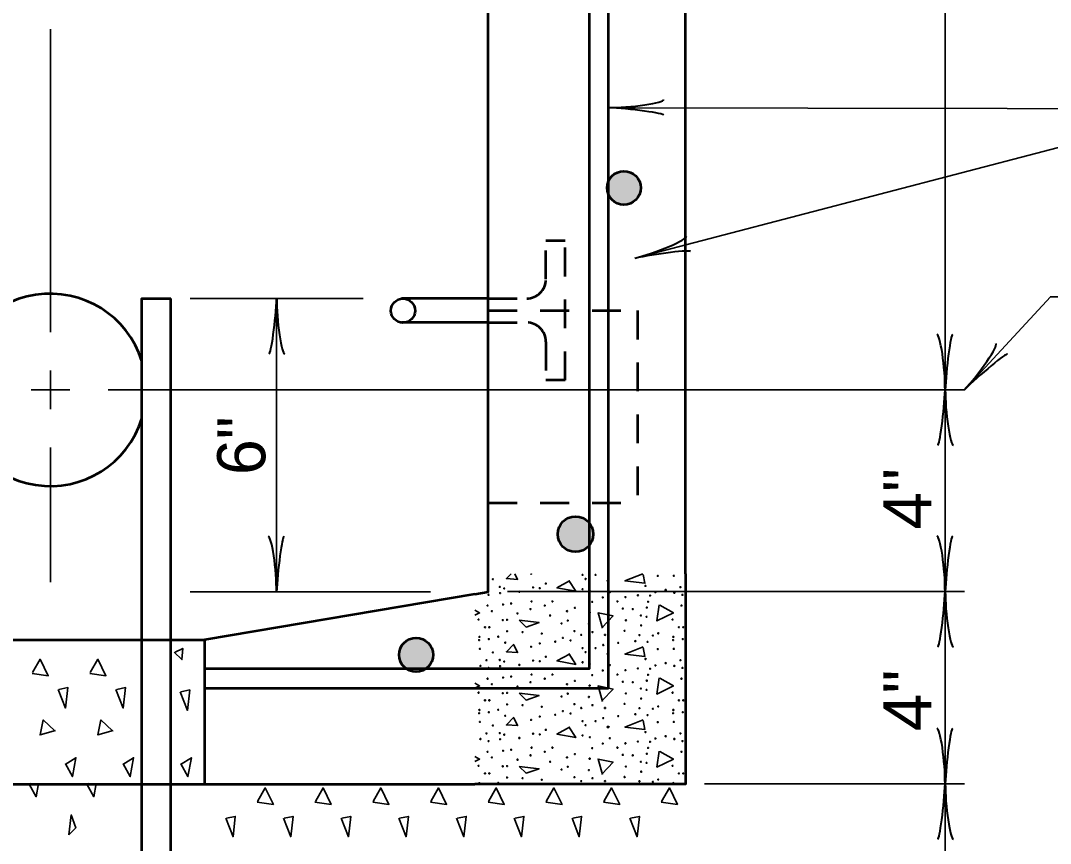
# Model space of a CAD drawing. Extents: x 788 to 1469, y -1 to 439.
# Drawn here: x 915.8 to 969.3, y 118.6 to 161.4 of the extents above; entities that cross this region are included whole.
import ezdxf

# ---------------------------------------------------------------- set-up
doc = ezdxf.new("R2010")
doc.units = 0
doc.linetypes.add('SHORT_DASHED', pattern=[2.7, 1.5, -1.2])
doc.layers.add('1', color=7, linetype='Continuous', lineweight=35)

msp = doc.modelspace()

# ---------------------------------------------------------------- hatches: boundary and pattern name
at = {"layer": '1'}
for points in [[(946.283, 152.704, 1), (948.034, 152.704, 1)], [(943.721, 134.704, 1), (945.568, 134.704, 1)], [(935.473, 128.43, 1), (937.243, 128.43, 1)]]:
    msp.add_hatch(color=256, dxfattribs=at).paths.add_polyline_path(points)

# ---------------------------------------------------------------- linework, layer by layer
at = {"layer": '1', "lineweight": 53}
for p, q in [((940.106, 132.643), (940.106, 165.102)), ((950.356, 132.643), (950.356, 165.102)), ((923.606, 112.203), (923.606, 146.953)), ((940.106, 146.953), (935.606, 146.953)), ((940.106, 145.703), (935.606, 145.703)), ((939.409, 131.585), (925.356, 129.203)), ((909.356, 129.203), (925.356, 129.203)), ((925.356, 129.203), (925.356, 121.703)), ((894.126, 121.703), (939.409, 121.703))]:
    msp.add_line(p, q, dxfattribs=at)
at = {"layer": '1'}
for p, q in [((917.356, 160.953), (917.356, 145.203)), ((933.606, 146.953), (924.606, 146.953)), ((929.106, 146.953), (929.106, 131.703)), ((917.356, 143.203), (917.356, 141.203)), ((916.356, 142.203), (918.356, 142.203)), ((920.356, 142.203), (964.856, 142.203)), ((917.356, 139.203), (917.356, 132.203)), ((937.106, 131.703), (924.606, 131.703)), ((941.106, 131.723), (964.856, 131.723)), ((916.333, 121.738), (916.231, 121.673)), ((919.333, 121.738), (919.231, 121.673)), ((951.356, 121.729), (964.856, 121.729))]:
    msp.add_line(p, q, dxfattribs=at)
at = {"layer": '1', "linetype": 'SHORT_DASHED', "lineweight": 53}
for p, q in [((943.106, 147.953), (943.106, 149.953)), ((940.106, 146.953), (942.106, 146.953)), ((940.106, 146.328), (947.866, 146.328)), ((947.866, 146.328), (947.866, 136.328)), ((940.106, 145.703), (942.106, 145.703)), ((943.106, 144.703), (943.106, 142.703)), ((944.106, 142.703), (943.106, 142.703)), ((940.106, 136.328), (947.866, 136.328))]:
    msp.add_line(p, q, dxfattribs=at)
at = {"layer": '1'}
for points in [[(963.856, 195.872), (963.856, 142.203), (963.856, 131.723), (963.856, 121.729), (963.856, 90.479)], [(947.731, 149.041), (977.44, 156.814), (946.356, 156.871)], [(964.856, 142.203), (969.329, 147.043), (972.657, 147.043)], [(941.293, 132.643), (941.054, 132.392), (941.634, 132.352), (941.488, 132.643)], [(944.334, 132.272), (943.674, 131.912), (944.654, 131.732), (944.294, 132.292)], [(948.134, 132.643), (947.214, 132.272), (948.254, 132.152), (948.154, 132.612)], [(939.409, 130.752), (939.654, 130.612), (939.409, 130.492)], [(946.054, 129.812), (945.814, 130.612), (946.594, 130.452), (946.034, 129.852)], [(949.034, 131.012), (949.734, 130.612), (948.874, 130.192), (948.994, 131.032)], [(923.787, 128.568), (924.187, 128.188), (924.227, 128.768), (923.827, 128.568)], [(941.434, 128.992), (941.054, 128.592), (941.634, 128.552), (941.434, 128.952)], [(944.334, 128.472), (943.674, 128.112), (944.654, 127.932), (944.294, 128.492)], [(948.154, 128.852), (947.214, 128.472), (948.254, 128.352), (948.154, 128.812)], [(916.417, 127.505), (916.817, 128.205), (917.237, 127.345), (916.397, 127.465)], [(919.417, 127.505), (919.817, 128.205), (920.237, 127.345), (919.397, 127.465)], [(939.409, 126.952), (939.654, 126.812), (939.409, 126.692)], [(949.034, 127.212), (949.734, 126.812), (948.874, 126.392), (948.994, 127.232)], [(917.757, 126.625), (918.137, 125.665), (918.257, 126.725), (917.797, 126.625)], [(920.757, 126.625), (921.137, 125.665), (921.257, 126.725), (920.797, 126.625)], [(924.097, 126.506), (924.477, 125.546), (924.597, 126.606), (924.137, 126.506)], [(946.054, 126.012), (945.814, 126.812), (946.594, 126.652), (946.034, 126.052)], [(917.617, 124.505), (916.817, 124.265), (916.977, 125.045), (917.577, 124.485)], [(920.617, 124.505), (919.817, 124.265), (919.977, 125.045), (920.577, 124.485)], [(941.434, 125.192), (941.054, 124.792), (941.634, 124.752), (941.434, 125.152)], [(948.154, 125.052), (947.214, 124.672), (948.254, 124.552), (948.154, 125.012)], [(944.334, 124.672), (943.674, 124.312), (944.654, 124.132), (944.294, 124.692)], [(939.409, 123.152), (939.654, 123.012), (939.409, 122.892)], [(949.034, 123.412), (949.734, 123.012), (948.874, 122.592), (948.994, 123.432)], [(918.137, 122.765), (918.497, 122.105), (918.677, 123.085), (918.117, 122.725)], [(921.137, 122.765), (921.497, 122.105), (921.677, 123.085), (921.117, 122.725)], [(924.137, 122.765), (924.497, 122.105), (924.677, 123.085), (924.117, 122.725)], [(946.054, 122.212), (945.814, 123.012), (946.594, 122.852), (946.034, 122.252)], [(916.251, 121.713), (916.611, 121.053), (916.737, 121.738)], [(919.251, 121.713), (919.611, 121.053), (919.737, 121.738)], [(928.121, 120.813), (928.521, 121.513), (928.942, 120.653), (928.101, 120.773)], [(931.121, 120.813), (931.521, 121.513), (931.942, 120.653), (931.101, 120.773)], [(934.121, 120.813), (934.521, 121.513), (934.942, 120.653), (934.101, 120.773)], [(937.121, 120.813), (937.521, 121.513), (937.942, 120.653), (937.101, 120.773)], [(940.121, 120.813), (940.521, 121.513), (940.942, 120.653), (940.101, 120.773)], [(943.121, 120.813), (943.521, 121.513), (943.942, 120.653), (943.101, 120.773)], [(946.121, 120.813), (946.521, 121.513), (946.942, 120.653), (946.101, 120.773)], [(949.121, 120.813), (949.521, 121.513), (949.942, 120.653), (949.101, 120.773)], [(926.462, 119.933), (926.841, 118.973), (926.962, 120.033), (926.501, 119.933)], [(929.462, 119.933), (929.841, 118.973), (929.962, 120.033), (929.501, 119.933)], [(932.462, 119.933), (932.841, 118.973), (932.962, 120.033), (932.501, 119.933)], [(935.462, 119.933), (935.841, 118.973), (935.962, 120.033), (935.501, 119.933)], [(938.462, 119.933), (938.841, 118.973), (938.962, 120.033), (938.501, 119.933)], [(941.462, 119.933), (941.841, 118.973), (941.962, 120.033), (941.501, 119.933)], [(944.462, 119.933), (944.841, 118.973), (944.962, 120.033), (944.501, 119.933)], [(947.462, 119.933), (947.841, 118.973), (947.962, 120.033), (947.501, 119.933)]]:
    msp.add_lwpolyline(points, dxfattribs=at)
at = {"layer": '1', "lineweight": 53}
msp.add_lwpolyline([(946.356, 126.703), (946.356, 187.287), (945.356, 187.287), (945.356, 127.703), (925.356, 127.703), (925.356, 126.703)], close=True, dxfattribs=at)
at = {"layer": '1', "linetype": 'SHORT_DASHED', "lineweight": 53}
msp.add_lwpolyline([(944.106, 142.703), (944.106, 149.953), (943.106, 149.953)], dxfattribs=at)
at = {"layer": '1', "lineweight": 53}
for points in [[(922.106, 112.203), (922.106, 146.953), (923.606, 146.953)], [(939.409, 131.585), (940.106, 131.703), (940.106, 132.643)], [(950.356, 132.643), (950.356, 121.703), (939.409, 121.703)]]:
    msp.add_lwpolyline(points, dxfattribs=at)
at = {"layer": '1'}
for points in [[(941.714, 130.232), (942.754, 130.112), (942.074, 129.872)], [(941.714, 126.432), (942.754, 126.312), (942.074, 126.072)], [(941.714, 122.632), (942.754, 122.512), (942.074, 122.272)], [(918.312, 119.073), (918.431, 120.113), (918.671, 119.433)]]:
    msp.add_lwpolyline(points, close=True, dxfattribs=at)
at = {"layer": '1', "lineweight": 53}
for centre, radius in [((947.159, 152.704), 0.875), ((935.676, 146.32), 0.625), ((944.644, 134.704), 0.924), ((936.358, 128.43), 0.885)]:
    msp.add_circle(centre, radius, dxfattribs=at)
at = {"layer": '1'}
for centre in [(940.349, 132.359), (945.009, 132.584), (945.168, 132.372), (945.685, 132.584), (946.308, 132.279), (946.361, 132.279), (948.918, 132.531), (949.753, 132.544), (940.707, 131.961), (940.94, 131.881), (941.722, 131.709), (942.438, 131.934), (942.782, 131.895), (943.1, 132.133), (945.009, 131.841), (945.393, 131.749), (946.427, 131.696), (948.282, 132.014), (948.799, 131.682), (949.329, 131.802), (949.78, 131.656), (950.098, 131.948), (940.124, 131.55), (940.72, 131.643), (942.358, 131.205), (943.445, 131.205), (945.512, 131.179), (946.056, 131.417), (946.824, 131.205), (947.235, 131.431), (947.885, 131.523), (948.415, 131.192), (948.521, 131.51), (950.204, 131.55), (940.071, 130.993), (940.296, 130.701), (940.879, 131.046), (941.298, 131.099), (941.629, 130.582), (942.305, 130.807), (943.047, 130.993), (944.2, 130.701), (944.611, 130.874), (945.38, 130.635), (947.103, 130.834), (947.62, 130.807), (948.349, 130.887), (950.151, 130.993), (939.607, 130.264), (940.86, 130.235), (941.086, 130.251), (943.326, 130.476), (943.922, 130.065), (944.24, 130.211), (947.262, 130.224), (948.044, 130.476), (948.335, 130.41), (949.687, 130.264), (939.938, 129.866), (940.164, 129.866), (941.086, 129.654), (941.894, 129.614), (942.888, 129.535), (944.585, 129.667), (945.34, 130.038), (945.526, 129.614), (947.196, 129.681), (948.057, 129.959), (948.945, 129.548), (950.018, 129.866), (950.244, 129.866), (939.634, 129.195), (939.647, 129.362), (940.137, 129.248), (940.628, 129.376), (940.993, 129.062), (942.782, 129.022), (943.591, 129.115), (943.988, 129.309), (944.386, 129.182), (944.943, 129.468), (946.175, 129.468), (946.864, 129.049), (947.752, 129.142), (947.964, 129.455), (948.388, 129.102), (948.667, 129.429), (949.714, 129.195), (949.727, 129.362), (950.217, 129.248), (939.673, 128.744), (940.349, 128.559), (942.332, 128.85), (945.009, 128.784), (945.168, 128.572), (945.685, 128.784), (946.082, 128.943), (946.308, 128.479), (946.361, 128.479), (948.918, 128.731), (949.753, 128.744), (940.018, 128.148), (940.707, 128.161), (940.94, 128.081), (941.722, 127.909), (942.438, 128.134), (942.782, 128.095), (943.1, 128.333), (945.009, 128.041), (945.393, 127.949), (948.282, 128.214), (949.329, 128.002), (950.098, 128.148), (939.7, 127.856), (940.124, 127.75), (940.72, 127.843), (942.358, 127.405), (943.445, 127.405), (945.512, 127.379), (946.056, 127.617), (946.427, 127.896), (946.824, 127.405), (947.235, 127.631), (947.885, 127.723), (948.415, 127.392), (948.521, 127.71), (948.799, 127.882), (949.78, 127.856), (950.204, 127.75), (940.071, 127.193), (940.296, 126.901), (940.879, 127.246), (941.298, 127.299), (942.305, 127.007), (943.047, 127.193), (944.2, 126.901), (944.611, 127.074), (945.38, 126.835), (947.103, 127.034), (947.62, 127.007), (948.349, 127.087), (950.151, 127.193), (939.607, 126.464), (940.86, 126.435), (941.086, 126.451), (941.629, 126.782), (943.326, 126.676), (944.24, 126.411), (947.262, 126.424), (948.044, 126.676), (948.335, 126.61), (949.687, 126.464), (939.938, 126.066), (940.164, 126.066), (941.086, 125.854), (941.894, 125.814), (943.922, 126.265), (944.585, 125.867), (945.34, 126.238), (945.526, 125.814), (947.196, 125.881), (948.057, 126.159), (950.018, 126.066), (950.244, 126.066), (939.634, 125.395), (939.647, 125.562), (940.137, 125.448), (940.628, 125.576), (940.993, 125.262), (942.888, 125.735), (943.591, 125.315), (943.988, 125.509), (944.386, 125.382), (944.943, 125.668), (946.175, 125.668), (946.864, 125.249), (947.752, 125.342), (947.964, 125.655), (948.388, 125.302), (948.667, 125.629), (948.945, 125.748), (949.714, 125.395), (949.727, 125.562), (950.217, 125.448), (939.673, 124.944), (940.349, 124.759), (942.332, 125.05), (942.782, 125.222), (945.009, 124.984), (945.168, 124.772), (945.685, 124.984), (946.082, 125.143), (948.918, 124.931), (949.753, 124.944), (940.018, 124.348), (940.707, 124.361), (940.94, 124.281), (942.438, 124.334), (942.782, 124.295), (943.1, 124.533), (945.009, 124.241), (946.308, 124.679), (946.361, 124.679), (948.282, 124.414), (949.329, 124.202), (950.098, 124.348), (939.7, 124.056), (940.124, 123.95), (940.72, 124.043), (941.722, 124.109), (945.393, 124.149), (946.056, 123.817), (946.427, 124.096), (947.235, 123.831), (947.885, 123.923), (948.521, 123.91), (948.799, 124.082), (949.78, 124.056), (950.204, 123.95), (940.071, 123.393), (940.296, 123.101), (940.879, 123.446), (941.298, 123.499), (942.305, 123.207), (942.358, 123.605), (943.047, 123.393), (943.445, 123.605), (944.2, 123.101), (944.611, 123.274), (945.512, 123.579), (946.824, 123.605), (947.103, 123.234), (947.62, 123.207), (948.349, 123.287), (948.415, 123.592), (950.151, 123.393), (939.607, 122.664), (940.86, 122.635), (941.086, 122.651), (941.629, 122.982), (943.326, 122.876), (944.24, 122.611), (945.38, 123.035), (947.262, 122.624), (948.044, 122.876), (948.335, 122.81), (949.687, 122.664), (939.938, 122.266), (940.164, 122.266), (941.086, 122.054), (941.894, 122.014), (943.922, 122.465), (944.585, 122.067), (945.34, 122.438), (945.526, 122.014), (947.196, 122.081), (948.057, 122.359), (950.018, 122.266), (950.244, 122.266), (939.647, 121.762), (940.628, 121.776), (942.888, 121.935), (944.943, 121.868), (946.175, 121.868), (947.964, 121.855), (948.667, 121.829), (948.945, 121.948), (949.727, 121.762)]:
    msp.add_circle(centre, 0.0265, dxfattribs=at)
at = {"layer": '1', "linetype": 'SHORT_DASHED', "lineweight": 53}
for centre, start, end in [((942.106, 147.953), 270, 0), ((942.106, 144.703), 0, 90)]:
    msp.add_arc(centre, 1, start, end, dxfattribs=at)
at = {"layer": '1', "lineweight": 53}
msp.add_arc((917.335, 142.203), 5, 17.3822, 342.6178, dxfattribs=at)
at = {"layer": '1'}
for centre, start, end in [((942.332, 132.65), 194.6794, 345.3206), ((939.7, 131.656), 244.3123, 314.9188), ((950.376, 130.701), 139.3543, 220.6457), ((950.376, 126.901), 139.3543, 220.6457), ((950.376, 123.101), 139.3543, 220.6457), ((943.988, 121.709), 345.7261, 194.2739)]:
    msp.add_arc(centre, 0.0265, start, end, dxfattribs=at)
at = {"layer": '1', "lineweight": 40}
for centre, major_axis, ratio, start_param, end_param in [((947.448, 157.146), (-1.786, -0.153), 0.122415, 0.896353, 3.141593), ((947.448, 157.146), (-1.786, -0.153), 0.122415, 0.896353, 3.141593), ((947.476, 156.658), (-1.756, 0.179), 0.07063, 3.140715, 5.41811), ((947.476, 156.658), (-1.756, 0.179), 0.07063, 3.140715, 5.41811), ((948.716, 149.585), (-1.688, -0.603), 0.122415, 0.896353, 3.141593), ((948.716, 149.585), (-1.688, -0.603), 0.122415, 0.896353, 3.141593), ((948.868, 149.12), (1.744, 0.275), 0.07063, 6.282307, 8.559703), ((948.868, 149.12), (1.744, 0.275), 0.07063, 6.282307, 8.559703), ((928.895, 145.832), (0.176, 1.756), 0.07063, 3.140715, 5.41811), ((928.895, 145.832), (0.176, 1.756), 0.07063, 3.140715, 5.41811), ((929.383, 145.862), (-0.156, 1.786), 0.122415, 0.896353, 3.141593), ((929.383, 145.862), (-0.156, 1.786), 0.122415, 0.896353, 3.141593), ((963.58, 143.294), (0.156, -1.786), 0.122415, 0.896353, 3.141593), ((963.58, 143.294), (0.156, -1.786), 0.122415, 0.896353, 3.141593), ((964.068, 143.323), (-0.176, -1.756), 0.07063, 3.140715, 5.41811), ((964.068, 143.323), (-0.176, -1.756), 0.07063, 3.140715, 5.41811), ((965.394, 143.192), (-1.097, -1.417), 0.122415, 0.896353, 3.141593), ((965.772, 142.882), (1.321, 1.171), 0.07063, 6.282307, 8.559703), ((963.645, 141.082), (0.176, 1.756), 0.07063, 3.140715, 5.41811), ((963.645, 141.082), (0.176, 1.756), 0.07063, 3.140715, 5.41811), ((964.133, 141.112), (-0.156, 1.786), 0.122415, 0.896353, 3.141593), ((964.133, 141.112), (-0.156, 1.786), 0.122415, 0.896353, 3.141593), ((928.83, 132.794), (0.156, -1.786), 0.122415, 0.896353, 3.141593), ((929.318, 132.823), (-0.176, -1.756), 0.07063, 3.140715, 5.41811), ((963.58, 132.814), (0.156, -1.786), 0.122415, 0.896353, 3.141593), ((964.068, 132.843), (-0.176, -1.756), 0.07063, 3.140715, 5.41811), ((963.645, 130.602), (0.176, 1.756), 0.07063, 3.140715, 5.41811), ((963.645, 130.602), (0.176, 1.756), 0.07063, 3.140715, 5.41811), ((964.133, 130.631), (-0.156, 1.786), 0.122415, 0.896353, 3.141593), ((964.133, 130.631), (-0.156, 1.786), 0.122415, 0.896353, 3.141593), ((963.58, 122.821), (0.156, -1.786), 0.122415, 0.896353, 3.141593), ((963.58, 122.821), (0.156, -1.786), 0.122415, 0.896353, 3.141593), ((964.068, 122.85), (-0.176, -1.756), 0.07063, 3.140715, 5.41811), ((964.068, 122.85), (-0.176, -1.756), 0.07063, 3.140715, 5.41811), ((963.645, 120.609), (0.176, 1.756), 0.07063, 3.140715, 5.41811), ((963.645, 120.609), (0.176, 1.756), 0.07063, 3.140715, 5.41811), ((964.133, 120.638), (-0.156, 1.786), 0.122415, 0.896353, 3.141593), ((964.133, 120.638), (-0.156, 1.786), 0.122415, 0.896353, 3.141593)]:
    msp.add_ellipse(centre, major_axis=major_axis, ratio=ratio, start_param=start_param, end_param=end_param, dxfattribs=at)

# ---------------------------------------------------------------- texts
at = {"layer": '1'}
msp.add_text('6"', height=2.5, rotation=90, dxfattribs=at).set_placement((928.519, 137.777))
at = {"layer": '1', "width": 1.05}
for p in [(963.141, 134.942), (963.141, 124.466)]:
    msp.add_text('4"', height=2.5, rotation=90, dxfattribs=at).set_placement(p)

doc.saveas('drawing.dxf')
